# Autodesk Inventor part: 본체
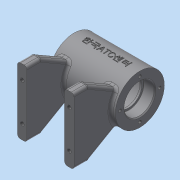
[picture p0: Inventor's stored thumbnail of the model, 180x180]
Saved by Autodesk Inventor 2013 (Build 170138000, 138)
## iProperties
Created: 2018-05
Part Number: 본체
Material: 일반
Document SubType Name: Modeling
Designer: dgall
Density: 1 g/cm^3
Author: dgall
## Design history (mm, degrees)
sketch "스케치1"
  geometry: L1 (-35, 0)-(35, 0); L2 (-35, 26)-(-35, 16); L3 (-35, 16)-(-23, 16); L4 (-23, 16)-(-23, 14); L5 (-23, 14)-(-21, 14); L6 (-21, 14)-(-21, 21); L7 (-21, 21)-(21, 21); L8 (21, 21)-(21, 14); L9 (21, 14)-(23, 14); L10 (23, 14)-(23, 16); L11 (23, 16)-(35, 16); L12 (35, 16)-(35, 26); L13 (35, 26)-(-35, 26); 2 further points
  constraints: 26 end point, 5 vertical, 4 horizontal, 2 horizontal alignment, 2 vertical alignment, 1 coincident, 1 midpoint
  dimensions: "d15" = 42 distance of L6.end L7.end; "d17" = 70 distance of L1.start L1.end; "d18" = 12 distance of L2.end L3.end; "d19" = 2 distance of L4.end L5.end; "d20" = 2 distance of L8.end L9.end; "d21" = 12 distance of L10.end L11.end; "d22" = 32 diameter of L3 L1; "d23" = 28 diameter of L5 L1; "d24" = 52 diameter of L13 L1; "d25" = 42 diameter of L7 L1
revolve "회전1" sketch "스케치1" stored, may be unused: angle "d26" = 90 deg
node "작업 평면1"
sketch "스케치2"
  geometry: L1 (-5, 23.029)-(-5, 29); L2 (-5, 29)-(0, 29); L3 (0, 23.029)-(-5, 23.029); L4 (0, 29)-(0, 0); C1 r 26 at (0, 0) reference; C2 r 21 at (0, 0) reference; 1 further point
  constraints: 8 end point, 2 horizontal, 2 vertical, 1 point on line
  dimensions: "d27" = 10 diameter of L1 L4; "d29" = 29 distance of L2.end point (0, 0); "d30" = 23.02906 distance from line of point (0, 0) L3
revolve "회전2" sketch "스케치2" stored, may be unused: angle "d31" = 90 deg
sketch "스케치3"
  geometry: L1 (0, 0)-(17.538, -48.184); L2 (0, 0)-(0, -46.16); L3 (13.163, -18.621)-(15.557, -25.199); L4 (15.557, -25.199)-(9.919, -27.251); L5 (13.163, -18.621)-(7.524, -20.673)
  constraints: 10 end point, 2 perpendicular, 2 point on line, 1 parallel, 1 vertical
  dimensions: "d32" = 20 deg angle of L2 L1; "d33" = 12 diameter of L3 L1; "d35" = 29 distance from line of L1.start L4; "d36" = 22 distance from line of L1.start L5
revolve "회전3" sketch "스케치3" stored, may be unused: angle "d37" = 90 deg
sketch "스케치4"
  geometry: C1 r 5 at (0, 0) reference; 1 further point
  constraints: 1 coincident
hole "구멍1" sketch "스케치4" at (0, 0) diameter "d38" = 5.188; stored, may be unused: countersink angle "d42" = 90 deg, drill point angle "d44" = 118 deg; dims "d39" = 6, "d40" = 4, "d41" = 2, "d43" = 20
node "작업 평면2"
sketch "스케치5"
  geometry: 1 further point
node "작업 평면3"
sketch "스케치6"
  geometry: L1 (-35, -65)-(35, -65); L2 (-35, -65)-(-35, -50); L3 (-35, -50)-(-16.278, -17.573); L4 (-16.278, -17.573)-(0, -24); L5 (0, -24)-(16.278, -17.573); L6 (16.278, -17.573)-(35, -50); L7 (35, -50)-(35, -65); C1 r 26 at (0, 0) reference; C2 r 21 at (0, 0) reference; 2 further points
  constraints: 14 end point, 2 horizontal alignment, 2 vertical alignment, 1 horizontal, 1 midpoint, 1 vertical
  dimensions: "d47" = 70 distance of L1.start L1.end; "d49" = 65 distance from line of point (0, 0) L1; "d50" = 15 distance of L6.end L1.end; "d51" = 15 distance of L1.start L2.end; "d52" = 30 deg angle of L2 L3; "d54" = 30 deg angle of L6 L7; "d55" = 6.42684 vertical distance of L4.end L5.end; "d56" = 16.27835 horizontal distance of L4.end L5.end
extrude "돌출1" join sketch "스케치6" distance "d57" = 10; taper "d58" = 0 deg
sketch "스케치7"
  geometry: C1 r 26 at (0, 0) reference; 3 further points
  constraints: 3 vertical alignment, 1 coincident, 3 other
hole "구멍2" sketch "스케치7" at (0, 21) diameter "d59" = 3.242; stored, may be unused: countersink angle "d63" = 90 deg, drill point angle "d65" = 118 deg; dims "d60" = 8, "d61" = 4, "d62" = 2, "d64" = 10
fillet "모깎기1" dims "d69" = 0.3
fillet "모깎기2" dims "d70" = 2
fillet "모깎기3" dims "d71" = 3
fillet "모깎기4" dims "d72" = 3
fillet "모깎기5" dims "d73" = 3
fillet "모깎기6" dims "d74" = 3
chamfer "모따기1" distance "d75" = 1; stored, may be unused: second distance "d76" = 2, angle "d77" = 45 deg
sketch "스케치8"
  geometry: L1 (3, 67)-(7, 67) reference; C1 r 4 at (5, 52); 3 further points
  constraints: 1 centre point, 1 coincident, 1 midpoint, 1 vertical alignment
  dimensions: "d78" = 20 vertical distance of point (-20, 32) C1.centre
hole "구멍3" sketch "스케치8" at (5, 52) diameter "d79" = 4.134; stored, may be unused: countersink angle "d83" = 90 deg, drill point angle "d85" = 118 deg; dims "d80" = 8, "d81" = 4, "d82" = 2, "d84" = 10
node "작업 평면4"
node "작업 평면5"
sketch "스케치9"
  geometry: L1 (-35, -26)-(-35, 26) reference; L2 (-35, 26)-(35, 26) reference; 2 further points
  constraints: 1 other
  dimensions: "d87" = 35 distance from line of L1 point (0, 0); "d88" = 26 distance from line of L2 point (0, 0)
feature "엠보싱1" sketch "스케치9" dims "d89" = 0.5, "d90" = 0
sketch "스케치10"
  geometry: C1 r 6 at (0, 0) reference; 1 further point
  constraints: 1 coincident
hole "구멍4" sketch "스케치10" at (0, 0) diameter "d91" = 5.188; stored, may be unused: countersink angle "d95" = 90 deg, drill point angle "d97" = 118 deg; dims "d92" = 8, "d93" = 4, "d94" = 2, "d96" = 20
node "솔리드1"
mirror "대칭1"
pattern_circular "원형 패턴1" dims angle "d67" = 360 deg
mirror "대칭2"
mirror "대칭3"
mirror "대칭4"
node "절단 모서리 투영1"
node "절단 모서리 투영2"
other parameters: "d45" = -65, "d86" = 55
